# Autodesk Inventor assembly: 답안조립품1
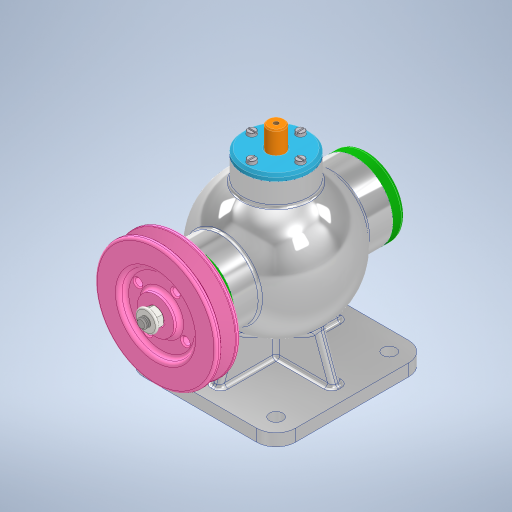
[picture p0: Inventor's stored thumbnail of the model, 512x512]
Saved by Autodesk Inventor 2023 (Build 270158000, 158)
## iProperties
Created: 2023-07
Part Number: 답안조립품1
Document SubType Name: Assembly
Designer: Owner
Author: Owner
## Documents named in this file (16)
- C:\Users\Owner\Desktop\730711V1006\답안조립품1.iam
- C:\Users\Owner\Desktop\730711V1006\본체.ipt
- C:\Users\Owner\Desktop\730711V1006\편심축.ipt
- C:\Users\Owner\Desktop\730711V1006\칼라.ipt
- C:\Users\Owner\Desktop\730711V1006\베어링- 6202.ipt
- KS B 2023 - 6202 - 15 x 35 x 11 - 7.8.ipt
- C:\Users\Owner\Desktop\730711V1006\앞커버.ipt
- C:\Users\Owner\Desktop\730711V1006\뒤커버.ipt
- C:\Users\Owner\Desktop\730711V1006\오일실 15 30 7.ipt
- C:\Users\Owner\Desktop\730711V1006\V-벨트풀리.ipt
- C:\Users\Owner\Desktop\730711V1006\키 4 x 4 x 12.ipt
- C:\Users\Owner\Desktop\730711V1006\너트 M8.ipt
- C:\Users\Owner\Desktop\730711V1006\슬라이드.ipt
- C:\Users\Owner\Desktop\730711V1006\상부커버.ipt
- C:\Users\Owner\Desktop\730711V1006\볼트 M4 x 16.ipt
- C:\Users\Owner\Desktop\730711V1006\볼트 M4 x 12.ipt
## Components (15 placed, 4 different names)
1. KS B 2023 - 6202 - 15 x 35 x 11 - 7.8:1
2. KS B 2023 - 6202 - 15 x 35 x 11 - 7.8:2
3. V-벨트풀리:1
4. ISO 4762 M4 x 16:1
5. ISO 4762 M4 x 16:3
6. ISO 4762 M4 x 16:4
7. ISO 4762 M4 x 16:5
8. ISO 4762 M4 x 16:2
9. ISO 4762 M4 x 16:6
10. ISO 4762 M4 x 16:7
11. ISO 4762 M4 x 16:8
12. KS B 1021 - 에 따름 ISO 1207 - 미터 A  M 4 x 12:1
13. KS B 1021 - 에 따름 ISO 1207 - 미터 A  M 4 x 12:2
14. KS B 1021 - 에 따름 ISO 1207 - 미터 A  M 4 x 12:3
15. KS B 1021 - 에 따름 ISO 1207 - 미터 A  M 4 x 12:4
